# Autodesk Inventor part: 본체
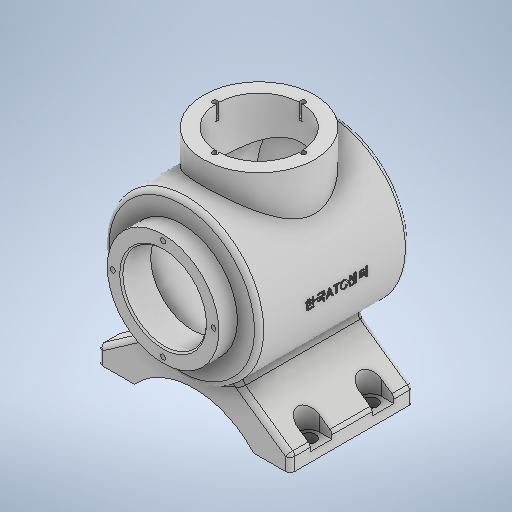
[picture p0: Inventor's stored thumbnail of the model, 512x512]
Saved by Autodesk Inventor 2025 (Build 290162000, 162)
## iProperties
Created: 2024-07
Part Number: 본체
Material: 일반
Document SubType Name: Modeling
Designer: hsj03
Density: 1 g/cm^3
Appearance: 기본값
Author: hsj03
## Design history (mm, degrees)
sketch "스케치9"
  geometry: C1 r 50 at (0, 0); 1 further point
  constraints: 1 centre point, 1 coincident
  dimensions: "d23" = 100 diameter of C1
extrude "돌출3" new body sketch "스케치9" stored distance "d24" = 108; taper "d25" = 0 deg
sketch "스케치10"
  geometry: L1 (-50, -54)-(50, -54) reference; L2 (50, 54)-(-50, 54) reference; L3 (50, -42.336)-(50, 54); L4 (50, 54)-(-7.913, 54); L5 (0, -54)-(0, 54); L6 (50, 54)-(0, 54); A1 r 113 centre (0, 59) between (0, -54) and (50, -42.336); 2 further points
  constraints: 8 end point, 2 midpoint, 2 point on circle, 2 point on line, 2 vertical, 1 centre point, 1 vertical alignment
  dimensions: "d26" = 226 diameter of A1
revolve "회전2" sketch "스케치10" stored, may be unused: angle "d27" = 360 deg
sketch "스케치11"
  geometry: C1 r 36 at (0, 0); 1 further point
  constraints: 1 centre point, 1 coincident
  dimensions: "d28" = 72 diameter of C1
extrude "돌출4" join sketch "스케치11" distance "d29" = 12; taper "d30" = 0 deg
fillet "모깎기1" dims "d31" = 3
feature "쉘1" dims "d32" = 7, "d99" = 9
node "작업 평면1"
sketch "스케치13"
  geometry: L1 (36, 66)-(-36, 66) reference; C1 r 36 at (0, 4); 1 further point
  constraints: 1 centre point
  dimensions: "d100" = 62 distance from line of L1 C1.centre; "d101" = 72 diameter of C1
extrude "돌출5" join sketch "스케치13" taper "d30" = 0 deg; stored distance "d35" = 12; taper "d36" = 0 deg
node "작업 평면2"
sketch "스케치14"
  geometry: L1 (-26.694, -42.278)-(-62, -67); L2 (-62, -67)-(-62, -77); L3 (-62, -77)-(-38.5, -77); L4 (26.694, -42.278)-(62, -67); L5 (62, -67)-(62, -77); L6 (62, -77)-(38.5, -77); L7 (0, 25.398)-(0, -122.418); L8 (-26.694, -42.278)-(26.556, -42.365); A1 r 50 centre (0, 0) between (-26.694, -42.278) and (26.694, -42.278) reference; A2 r 52.096 centre (0, -112.096) between (38.5, -77) and (-38.5, -77); 2 further points
  constraints: 16 end point, 6 point on circle, 3 vertical, 2 perpendicular, 2 point on line, 1 centre point, 1 midpoint, 3 other
  dimensions: "d38" = 10 distance of L4.end L5.end; "d39" = 17 vertical distance of L6.end point (0, -60); "d40" = 77 distance of L3.end L6.end; "d41" = 77 vertical distance of point (50.25, -77) A1.centre; "d42" = 55 deg angle of L5 L4; "d43" = 124 distance between parallel lines of L5 L2
extrude "돌출6" join sketch "스케치14" distance "d44" = 80; taper "d45" = 0 deg
sketch "스케치15"
  geometry: C1 r 36 at (0, 0) reference; 1 further point
  constraints: 1 coincident
hole "구멍1" sketch "스케치15" at (0, 0) diameter "d46" = 54; stored, may be unused: countersink angle "d50" = 90 deg, drill point angle "d52" = 0 deg; dims "d47" = 6, "d48" = 4, "d49" = 2, "d51" = 50
node "작업 평면3"
sketch "스케치16" dims "d54" = 14
  geometry: L1 (-38.5, -100.641)-(-38.5, 25.831); L2 (-111.678, -40)-(58.457, -40); L3 (23.5, 0)-(23.5, -80) reference; L4 (-100.5, -67)-(-92.5, -67); L5 (-92.5, -67)-(-92.5, -53); L6 (-92.5, -53)-(-100.5, -53); L7 (-100.5, -53)-(-100.5, -67); L8 (-100.5, -67)-(-92.5, -53); L9 (-92.5, -67)-(-100.5, -53); L10 (-100.5, 0)-(-100.5, -80) reference; L11 (-100.5, -27)-(-92.5, -27); L12 (-92.5, -27)-(-92.5, -13); L13 (-92.5, -13)-(-100.5, -13); L14 (-100.5, -13)-(-100.5, -27); L15 (-100.5, -27)-(-92.5, -13); L16 (-92.5, -27)-(-100.5, -13); L17 (15.5, -67)-(23.5, -67); L18 (23.5, -67)-(23.5, -53); L19 (23.5, -53)-(15.5, -53); L20 (15.5, -53)-(15.5, -67); L21 (15.5, -67)-(23.5, -53); L22 (23.5, -67)-(15.5, -53); L23 (15.5, -27)-(23.5, -27); L24 (23.5, -27)-(23.5, -13); L25 (23.5, -13)-(15.5, -13); L26 (15.5, -13)-(15.5, -27); L27 (15.5, -27)-(23.5, -13); L28 (23.5, -27)-(15.5, -13); 22 further points
  constraints: 52 end point, 13 midpoint, 8 parallel, 5 horizontal, 4 coincident, 4 perpendicular, 4 symmetric about line, 3 collinear, 2 point on line, 1 vertical, 12 other
  dimensions: "d55" = 40 distance of point (15.5, -20) point (15.5, -60); "d56" = 8 distance from line of L3 point (15.5, -60)
extrude "돌출7" cut sketch "스케치16" distance "d57" = 50; taper "d58" = 0 deg
sketch "스케치17" dims "d66" = 65
  geometry: C1 r 36 at (0, 0) reference; 2 further points
  constraints: 2 vertical alignment, 1 coincident, 2 other
hole "구멍2" sketch "스케치17" at (0, 32.5) diameter "d59" = 3.242; stored, may be unused: countersink angle "d63" = 90 deg, drill point angle "d65" = 120 deg; dims "d60" = 8, "d61" = 4, "d62" = 2, "d64" = 10
sketch "스케치18" dims "d77" = 65
  geometry: C1 r 27 at (0, 0) reference; C2 r 36 at (0, 0) reference; 3 further points
  constraints: 2 vertical alignment, 1 coincident, 2 other
hole "구멍3" sketch "스케치18" at (0, -28.5) diameter "d70" = 3.242; stored, may be unused: countersink angle "d74" = 90 deg, drill point angle "d76" = 120 deg; dims "d71" = 8, "d72" = 4, "d73" = 2, "d75" = 10
sketch "스케치19"
  geometry: A1 r 7 centre (-92.5, 20) between (-92.5, 13) and (-92.5, 27) reference; A2 r 7 centre (-92.5, 60) between (-92.5, 53) and (-92.5, 67) reference; A3 r 7 centre (15.5, 60) between (15.5, 67) and (15.5, 53) reference; A4 r 7 centre (15.5, 20) between (15.5, 27) and (15.5, 13) reference; 4 further points
  constraints: 4 coincident
hole "구멍4" sketch "스케치19" at (-92.5, 20), (-92.5, 60), (15.5, 60), (15.5, 20) diameter "d81" = 9; stored, may be unused: countersink angle "d85" = 90 deg, drill point angle "d87" = 0 deg; dims "d82" = 8, "d83" = 4, "d84" = 2, "d86" = 10
fillet "모깎기5" dims "d91" = 3
fillet "모깎기4" dims "d90" = 3
fillet "모깎기2" dims "d88" = 3
chamfer "모따기1" distance "d92" = 1; stored, may be unused: second distance "d93" = 2, angle "d94" = 45 deg
node "작업 평면4"
sketch "스케치20"
  geometry: L1 (36, 66)-(-36, 66) reference; 2 further points
  constraints: 1 vertical alignment, 1 other
  dimensions: "d96" = 62 distance from line of L1 point (0, 4)
feature "엠보싱1" sketch "스케치20" dims "d97" = 0.5, "d98" = 0
node "솔리드4"
pattern_circular "원형 패턴1" dims angle "d68" = 360 deg
pattern_circular "원형 패턴2" dims angle "d79" = 360 deg
node "투영된 루프1"
node "투영된 루프2"
feature "A9D066F2-1C7D-4E18-AEED-F7BC21143FA4" dims "d46" = 54, "d47" = 6, "d48" = 4, "d49" = 2, "d50" = 90 deg, "d51" = 50, "d52" = 0
other parameters: "d17" = 226, "d33" = 65, "d53" = -6, "d95" = 116.5
